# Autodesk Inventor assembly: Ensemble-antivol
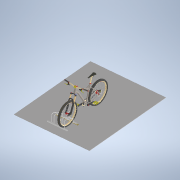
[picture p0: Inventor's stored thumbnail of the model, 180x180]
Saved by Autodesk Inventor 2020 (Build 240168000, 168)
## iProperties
Created: 2021-01
Part Number: Ensemble-antivol
Document SubType Name: Assembly
Designer: bruno
Author: bruno
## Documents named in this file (3)
- C:\Users\bruno\Documents\1-Cours-2020-21\1STI2D-2020-21\IT\6. Antivol\Inventor-Antivol\Ensemble-antivol.iam
- C:\Users\bruno\Documents\1-Cours-2020-21\1STI2D-2020-21\IT\6. Antivol\Inventor-Antivol\Ratelier.iam
- C:\Users\bruno\Documents\1-Cours-2020-21\1STI2D-2020-21\IT\6. Antivol\Inventor-Antivol\INVENTOR 2018_Steel Hardtail B+\Vélo.iam
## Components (2 placed, 2 different names)
1. Ratelier:1 [sub-assembly] — Tangente:1, Tangente:2, Tangente:3, Affleurement:1
2. Vélo:1 [sub-assembly] — Tangente:1, Tangente:2, Tangente:3, Affleurement:1
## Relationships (4: Tangent 3, Flush 1)
- Tangente:1: Ratelier:1 ↔ Vélo:1
- Tangente:2: Ratelier:1 ↔ Vélo:1
- Tangente:3: Ratelier:1 ↔ Vélo:1
- Affleurement:1 [Flush]: Ratelier:1 ↔ Vélo:1
